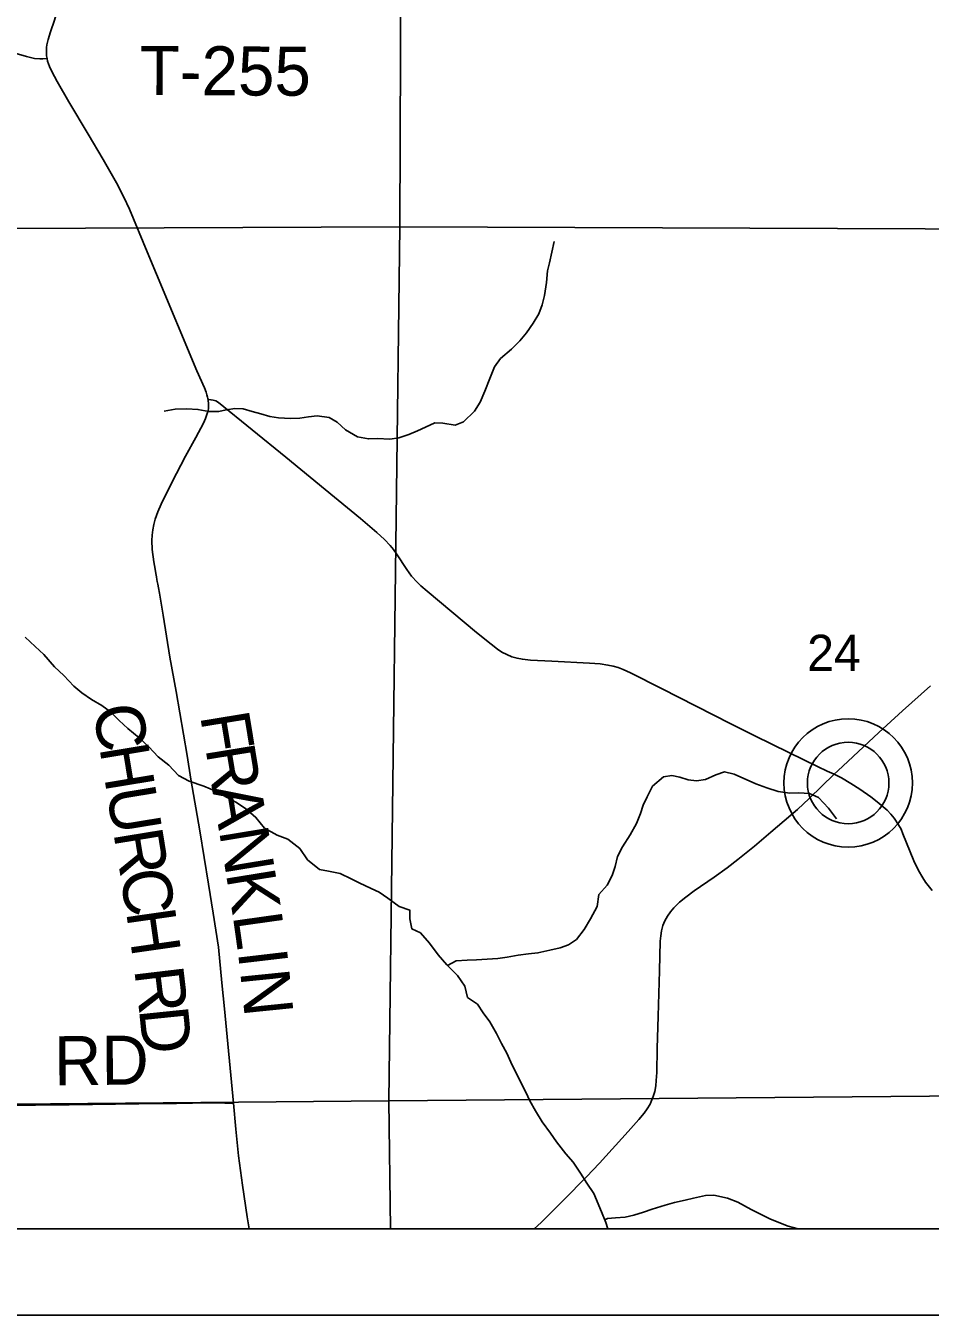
# Model space of a CAD drawing. Extents: x 0 to 34, y 0 to 22.
# Drawn here: x 3.99 to 5.038, y 14 to 15.494 of the extents above; entities that cross this region are included whole.
import ezdxf

# ---------------------------------------------------------------- set-up
doc = ezdxf.new("R2010")
doc.units = 0
for name, color, linetype in [('Default', 7, 'Continuous'), ('GM_X_County_Road', 7, 'Continuous'), ('GM_X_County_Road_Text', 7, 'Continuous'), ('GM_X_Minor_River', 7, 'Continuous'), ('GM_X_Section', 7, 'Continuous'), ('GM_X_Section_Text', 7, 'Continuous'), ('GM_X_State_Route', 7, 'Continuous'), ('GM_X_Township_Road', 7, 'Continuous'), ('GM_X_Township_Road_Text', 7, 'Continuous'), ('GM_X_Unincorporated', 7, 'Continuous'), ('GM_X_Unincorporated_Location', 7, 'Continuous'), ('SH_Cut_Line', 7, 'Continuous'), ('SH_Data', 7, 'Continuous')]:
    doc.layers.add(name, color=color, linetype=linetype)

msp = doc.modelspace()

# ---------------------------------------------------------------- linework, layer by layer
at = {"layer": 'Default'}
for points in [[(4.4126, 14.1), (5.4393, 14.1), (5.4396, 14.2573), (4.4107, 14.2482)], [(3.4083, 14.1), (4.4126, 14.1), (4.4107, 14.2482), (3.4079, 14.2395)]]:
    msp.add_lwpolyline(points, close=True, dxfattribs=at)
msp.add_lwpolyline([(3.4093, 14.1), (7.4893, 14.1)], dxfattribs=at)
at = {"layer": 'GM_X_County_Road'}
for points in [[(4.0146, 15.4558), (4.0141, 15.4589), (4.0139, 15.462), (4.0139, 15.4652), (4.0141, 15.4684), (4.0145, 15.4715), (4.0159, 15.4777), (4.0187, 15.4867), (4.0233, 15.5003), (4.0246, 15.5056), (4.0255, 15.5094), (4.0262, 15.5135)], [(4.2011, 15.0607), (4.2009, 15.0621), (4.2005, 15.0634), (4.1998, 15.0663), (4.1989, 15.0691), (4.1969, 15.0742), (4.1882, 15.0941), (4.1415, 15.206), (4.1306, 15.2318), (4.1101, 15.2814), (4.1036, 15.2952), (4.0949, 15.3119), (4.0797, 15.3389), (4.0624, 15.3683), (4.0399, 15.4058), (4.0263, 15.4293), (4.02, 15.4409), (4.0173, 15.4466), (4.0161, 15.4496), (4.0152, 15.4526), (4.0146, 15.4558)], [(4.2305, 14.2456), (4.2203, 14.3547), (4.2173, 14.3852), (4.2131, 14.4263), (4.2072, 14.4657), (4.2017, 14.4994), (4.1917, 14.561), (4.1813, 14.6211), (4.1769, 14.6482), (4.1642, 14.7224), (4.157, 14.7622), (4.149, 14.8108), (4.1449, 14.8366), (4.1436, 14.8428), (4.1428, 14.8467), (4.1422, 14.8499), (4.1418, 14.8523), (4.1413, 14.8553), (4.1406, 14.8594), (4.1398, 14.8644), (4.1385, 14.8729), (4.1365, 14.8871), (4.1361, 14.8973), (4.1363, 14.9036), (4.137, 14.9099), (4.1383, 14.916), (4.14, 14.922), (4.1431, 14.9308), (4.1468, 14.9395), (4.1592, 14.9648), (4.1752, 14.9951), (4.187, 15.0169), (4.1957, 15.0333), (4.1983, 15.0389), (4.2003, 15.0447), (4.2011, 15.0476), (4.2015, 15.0506), (4.2016, 15.052), (4.2017, 15.0539), (4.2016, 15.057), (4.2014, 15.059), (4.2011, 15.0607)], [(3.4078, 14.2398), (3.4343, 14.2398), (3.5586, 14.24), (3.5865, 14.2403), (3.6207, 14.2409), (3.6891, 14.2412), (3.7668, 14.2425), (3.829, 14.2428), (3.9005, 14.2433), (3.9626, 14.243), (4.0403, 14.2435), (4.1211, 14.2448), (4.1646, 14.2453), (4.2019, 14.2459), (4.2206, 14.2457), (4.2305, 14.2456)], [(4.2488, 14.1), (4.2464, 14.1138), (4.2409, 14.1508), (4.2366, 14.1847), (4.2333, 14.2156), (4.2305, 14.2456)]]:
    msp.add_lwpolyline(points, dxfattribs=at)
at = {"layer": 'GM_X_Minor_River'}
for points in [[(4.6023, 15.244), (4.5966, 15.2193), (4.5943, 15.2098), (4.5932, 15.1962), (4.5909, 15.1814), (4.5882, 15.1704), (4.5844, 15.1601), (4.578, 15.1491), (4.57, 15.1381), (4.5624, 15.1286), (4.5529, 15.1192), (4.54, 15.1082), (4.5332, 15.0987), (4.5275, 15.085), (4.5218, 15.0706), (4.5165, 15.0577), (4.5097, 15.0471), (4.4972, 15.0349), (4.4873, 15.0312), (4.4733, 15.0334), (4.4638, 15.0338), (4.4532, 15.0289), (4.4437, 15.0243), (4.4339, 15.0201), (4.4221, 15.0164), (4.4119, 15.0148), (4.3975, 15.0156), (4.3869, 15.0152), (4.3743, 15.0175), (4.3603, 15.0258), (4.3509, 15.0345), (4.3414, 15.0399), (4.3274, 15.0418), (4.3175, 15.0406), (4.3073, 15.0391), (4.2966, 15.0387), (4.2826, 15.0395), (4.2728, 15.041), (4.2622, 15.044), (4.2523, 15.0467), (4.2417, 15.0501), (4.2322, 15.0505), (4.2227, 15.0489), (4.2133, 15.0467), (4.2019, 15.0467), (4.1894, 15.0493), (4.1765, 15.0501), (4.1632, 15.0497), (4.1503, 15.0474)], [(3.9891, 14.7853), (4.0008, 14.7747), (4.0107, 14.7652), (4.0232, 14.7512), (4.0342, 14.7409)], [(4.0342, 14.7409), (4.0455, 14.7288), (4.055, 14.7208), (4.066, 14.7132), (4.0781, 14.7064), (4.088, 14.6988), (4.0982, 14.689), (4.1081, 14.6795), (4.1213, 14.6689), (4.1327, 14.6586), (4.1433, 14.6469), (4.1558, 14.637), (4.1668, 14.6253), (4.1793, 14.6188), (4.1964, 14.6127), (4.2108, 14.6067), (4.2225, 14.6002), (4.2335, 14.5942), (4.2445, 14.587), (4.2566, 14.5767), (4.2665, 14.5642), (4.2812, 14.5559), (4.2937, 14.5513), (4.3074, 14.5407), (4.3165, 14.5274), (4.3301, 14.5164), (4.3407, 14.5142), (4.3544, 14.5115), (4.3669, 14.5054), (4.3764, 14.5009), (4.39, 14.4941), (4.3995, 14.4899), (4.4093, 14.4831), (4.4226, 14.4736), (4.4351, 14.469), (4.4351, 14.4592), (4.4374, 14.4474), (4.4472, 14.4429), (4.4578, 14.4311), (4.4677, 14.4174), (4.4779, 14.4057), (4.49, 14.3936), (4.4987, 14.381), (4.5018, 14.3681), (4.5135, 14.3602), (4.52, 14.3503), (4.5275, 14.3397), (4.5355, 14.3264), (4.5412, 14.3147), (4.5472, 14.3037), (4.5518, 14.2931), (4.5639, 14.2688), (4.5692, 14.2585), (4.5741, 14.2483), (4.5805, 14.2369), (4.5881, 14.224), (4.598, 14.2108), (4.6048, 14.2009), (4.6158, 14.1869), (4.6241, 14.1774), (4.6328, 14.1645), (4.64, 14.1531), (4.648, 14.141), (4.6571, 14.1197), (4.662, 14.1072), (4.6645, 14.1)], [(4.4787, 14.4049), (4.4885, 14.4106), (4.5014, 14.4114), (4.512, 14.4118), (4.5245, 14.4125), (4.5367, 14.4133), (4.5477, 14.4148), (4.5605, 14.4171), (4.5723, 14.4186), (4.5833, 14.4197), (4.5973, 14.4228), (4.6091, 14.4254), (4.6186, 14.4292), (4.628, 14.4353), (4.6368, 14.4467), (4.6443, 14.4592), (4.6519, 14.4736), (4.6538, 14.4873), (4.6637, 14.4983), (4.6694, 14.5093), (4.6728, 14.5199), (4.6755, 14.5313), (4.6812, 14.5426), (4.6903, 14.5563), (4.6975, 14.5696), (4.702, 14.5813), (4.7054, 14.5908), (4.71, 14.6003), (4.7161, 14.6128), (4.729, 14.6238), (4.7384, 14.6253), (4.7479, 14.6231), (4.7574, 14.62), (4.7669, 14.6189), (4.7775, 14.6204), (4.7896, 14.6261), (4.7995, 14.6295), (4.8108, 14.6269), (4.8359, 14.6155), (4.8484, 14.6109), (4.8616, 14.6068), (4.8753, 14.6049), (4.8855, 14.6053), (4.898, 14.6045), (4.9083, 14.5996), (4.92, 14.5874), (4.9291, 14.5749)], [(4.6607, 14.1106), (4.6639, 14.1121), (4.6734, 14.1129), (4.6843, 14.1137), (4.6946, 14.1159), (4.7056, 14.1194), (4.7158, 14.1228), (4.7306, 14.1273), (4.7416, 14.1307), (4.7541, 14.1334), (4.7636, 14.1357), (4.7776, 14.1387), (4.7871, 14.1391), (4.803, 14.1357), (4.8148, 14.1308), (4.8303, 14.1224), (4.8413, 14.1171), (4.8519, 14.1118), (4.8625, 14.1072), (4.8731, 14.1031), (4.8849, 14.1)]]:
    msp.add_lwpolyline(points, dxfattribs=at)
at = {"layer": 'GM_X_Section'}
for points in [[(3.434, 16.2663), (4.4273, 16.2727), (4.4235, 15.2608), (3.4219, 15.2567), (3.4363, 15.7808)], [(4.4273, 16.2727), (5.4328, 16.2708), (5.4377, 15.2688), (5.4377, 15.257), (4.4235, 15.2608)], [(4.4235, 15.2608), (4.4107, 14.2482), (3.4079, 14.2395), (3.4219, 15.2567)], [(4.4235, 15.2608), (5.4377, 15.257), (5.4396, 14.2573), (4.4107, 14.2482)]]:
    msp.add_lwpolyline(points, close=True, dxfattribs=at)
at = {"layer": 'GM_X_State_Route'}
for points in [[(4.5914, 14.1117), (4.6135, 14.1338), (4.6397, 14.1603), (4.6547, 14.1761), (4.688, 14.2129), (4.7004, 14.2268), (4.7063, 14.2341), (4.71, 14.2392), (4.7132, 14.2446), (4.7146, 14.2474), (4.7169, 14.2532), (4.7186, 14.2593), (4.7198, 14.2655), (4.7205, 14.2717), (4.721, 14.2811), (4.7216, 14.309), (4.7227, 14.3463), (4.7242, 14.3991), (4.7251, 14.4333), (4.7256, 14.4394), (4.7265, 14.4454), (4.7281, 14.4513), (4.7304, 14.4569), (4.7333, 14.4623), (4.7369, 14.4672), (4.7409, 14.4719), (4.7475, 14.4784), (4.7546, 14.4843), (4.7645, 14.4916), (4.7875, 14.5075), (4.8027, 14.5184), (4.8151, 14.5278), (4.8344, 14.5434), (4.8532, 14.5597), (4.8839, 14.5859), (4.8976, 14.5985), (4.9266, 14.6267), (4.9307, 14.6307), (4.9785, 14.6751), (4.9874, 14.6836), (5.0058, 14.7001), (5.038, 14.7292)], [(4.5791, 14.1), (4.5871, 14.1075), (4.5914, 14.1117)]]:
    msp.add_lwpolyline(points, dxfattribs=at)
at = {"layer": 'GM_X_Township_Road'}
for points in [[(3.8599, 15.4815), (3.8744, 15.481), (3.9147, 15.481), (3.9271, 15.4807), (3.9333, 15.48), (3.9394, 15.4788), (3.9423, 15.4779), (3.948, 15.4754), (3.9589, 15.4695), (3.9645, 15.4669), (3.979, 15.4615), (3.9909, 15.458), (3.9999, 15.4559), (4.0062, 15.4555), (4.0097, 15.4556), (4.0146, 15.4558)], [(4.9266, 14.6267), (4.9185, 14.6302), (4.9072, 14.6355), (4.8739, 14.652), (4.8347, 14.6711), (4.8069, 14.6849), (4.7267, 14.7261), (4.6906, 14.7441), (4.6822, 14.748), (4.6764, 14.7502), (4.6705, 14.7519), (4.6645, 14.7532), (4.6554, 14.7545), (4.643, 14.7555), (4.5996, 14.7575), (4.5747, 14.7587), (4.5654, 14.7598), (4.5592, 14.761), (4.5532, 14.7628), (4.5473, 14.7652), (4.5417, 14.768), (4.5364, 14.7714), (4.529, 14.7772), (4.5121, 14.791), (4.4549, 14.8388), (4.4478, 14.845), (4.4433, 14.8493), (4.437, 14.8563), (4.4314, 14.8638), (4.4195, 14.882), (4.4159, 14.887), (4.412, 14.8918), (4.4057, 14.8985), (4.3966, 14.9069), (4.3777, 14.923), (4.3369, 14.9565), (4.2912, 14.9939), (4.2131, 15.0575), (4.21, 15.0591), (4.207, 15.06), (4.2044, 15.0605), (4.2011, 15.0607)], [(5.04, 14.492), (5.0324, 14.5017), (5.0292, 14.5068), (5.0241, 14.515), (5.019, 14.5262), (5.0063, 14.5575), (5.0042, 14.5629), (5.0012, 14.5682), (4.9962, 14.5757), (4.9924, 14.5805), (4.9881, 14.5849), (4.9763, 14.5948), (4.9689, 14.6005), (4.9562, 14.6094), (4.9458, 14.6161), (4.9352, 14.6225), (4.9298, 14.6253), (4.9266, 14.6267)]]:
    msp.add_lwpolyline(points, dxfattribs=at)
at = {"layer": 'GM_X_Unincorporated'}
for radius in [0.0744, 0.0472]:
    msp.add_circle((4.9428, 14.6166), radius, dxfattribs=at)
at = {"layer": 'GM_X_Unincorporated_Location'}
msp.add_line((4.9428, 14.6166), (4.9428, 14.6166), dxfattribs=at)
at = {"layer": 'SH_Cut_Line'}
msp.add_lwpolyline([(2.1, 14.1), (7.4893, 14.1)], dxfattribs=at)
at = {"layer": 'SH_Data'}
for p, q in [((2.1, 14.1), (8.9, 14.1)), ((2, 14), (9, 14))]:
    msp.add_line(p, q, dxfattribs=at)

# ---------------------------------------------------------------- texts
at = {"layer": 'GM_X_County_Road_Text'}
for s, height, rotation, p in [('C', 0.0568, 279.3379, (4.0675, 14.7039)), ('F', 0.0568, 279.3155, (4.1918, 14.6947)), ('H', 0.0568, 279.3378, (4.0751, 14.6579)), ('R', 0.0568, 279.3141, (4.198, 14.6568)), ('U', 0.0568, 279.3378, (4.0832, 14.6085)), ('A', 0.0568, 279.312, (4.2056, 14.6108)), ('N', 0.0568, 279.3143, (4.2137, 14.5614)), ('R', 0.0568, 279.2949, (4.0913, 14.5592)), ('C', 0.0568, 279.0138, (4.0988, 14.5132)), ('K', 0.0568, 279.2234, (4.2217, 14.5121)), ('H', 0.0568, 278.1801, (4.1061, 14.4674)), ('L', 0.0568, 277.9974, (4.2297, 14.4631)), ('I', 0.0568, 276.7203, (4.2356, 14.4213)), ('R', 0.0568, 276.8031, (4.1155, 14.4009)), ('N', 0.0568, 275.7835, (4.2383, 14.3984)), ('D', 0.0568, 275.8567, (4.121, 14.3548)), ('RD', 0.05682, 0.4936, (4.0229, 14.2663))]:
    msp.add_text(s, height=height, rotation=rotation, dxfattribs=at).set_placement(p)
at = {"layer": 'GM_X_Section_Text'}
msp.add_text('24', height=0.04186, rotation=0, dxfattribs=at).set_placement((4.8952, 14.7464))
at = {"layer": 'GM_X_Township_Road_Text'}
msp.add_text('T-255', height=0.05682, rotation=359.7176, dxfattribs=at).set_placement((4.1217, 15.4136))

doc.saveas('drawing.dxf')
